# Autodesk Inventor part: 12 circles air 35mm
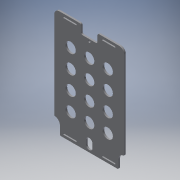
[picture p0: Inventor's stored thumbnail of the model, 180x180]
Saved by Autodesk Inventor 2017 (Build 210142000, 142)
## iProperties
Created: 2014-05
Part Number: 12 circles air 35mm
Material: Generic
Document SubType Name: Modeling
Designer: Designer
Density: 1 g/cm^3
Appearance: Default
Author: Designer
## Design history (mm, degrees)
sketch "Sketch1"
  geometry: L1 (77.642, -1.315)-(77.622, 8.185); L2 (61.622, 8.152)-(61.642, -1.348); L3 (-15.128, 22.543)-(-15.128, 233.169); L4 (49.622, 241.669)-(49.622, 227.669); L5 (53.622, 223.669)-(85.622, 223.669); L6 (89.622, 227.669)-(89.622, 241.669); L7 (-1.128, 6.669)-(-1.128, -12.331); L8 (140.372, 6.669)-(140.372, -12.331); L9 (0.872, -14.331)-(138.372, -14.331); L10 (154.372, 22.543)-(154.372, 233.169); L11 (45.622, 245.669)-(-2.628, 245.669); L12 (93.622, 245.669)-(141.872, 245.669); C1 r 3 at (69.622, 218.669); A1 r 8 centre (69.622, 8.169) between (77.622, 8.185) and (61.622, 8.152); A2 r 8 centre (69.642, -1.331) between (61.642, -1.348) and (77.642, -1.315); A3 r 4 centre (45.622, 241.669) between (49.622, 241.669) and (45.622, 245.669); A4 r 4 centre (53.622, 227.669) between (49.622, 227.669) and (53.622, 223.669); A5 r 4 centre (85.622, 227.669) between (85.622, 223.669) and (89.622, 227.669); A6 r 4 centre (93.622, 241.669) between (93.622, 245.669) and (89.622, 241.669); A7 r 14 centre (-15.128, 6.669) between (-1.128, 6.669) and (-13.378, 20.559); A8 r 2 centre (0.872, -12.331) between (-1.128, -12.331) and (0.872, -14.331); A9 r 14 centre (154.372, 6.669) between (152.622, 20.559) and (140.372, 6.669); A10 r 2 centre (138.372, -12.331) between (138.372, -14.331) and (140.372, -12.331); A11 r 2 centre (-13.128, 22.543) between (-15.128, 22.543) and (-13.378, 20.559); A12 r 2 centre (152.372, 22.543) between (152.622, 20.559) and (154.372, 22.543); A13 r 12.5 centre (-2.628, 233.169) between (-2.628, 245.669) and (-15.128, 233.169); A14 r 12.5 centre (141.872, 233.169) between (154.372, 233.169) and (141.872, 245.669); 12 further points
  constraints: 30 point on circle, 24 end point, 20 tangent, 15 centre point, 8 point on line, 4 vertical, 2 horizontal, 2 perpendicular, 2 vertical alignment, 1 midpoint, 1 parallel
  dimensions: "d111" = 5 distance from line of L5 C1.centre; "d191" = 14 distance between parallel lines of L7 L3; "d193" = 2 radius of A8 (derived); "d196" = 35 distance from line of L9 point (-15.128, 20.669); "d198" = 169.5 distance between parallel lines of L10 L3; "d199" = 260 distance between parallel lines of L9 L11; "d200" = 2 radius of A11 (derived); "d201" = 2 radius of A12 (derived); "d202" = 20 distance from line of C1.centre L4; "d203" = 12.5 radius of A13; "d244" = 4 radius of A4; "d245" = 4 radius of A5; "d246" = 4 radius of A3; "d247" = 4 radius of A6; "d248" = 215.5 distance from line of A1.centre L5; "d249" = 9.5 vertical distance of L2.start L2.end; "d250" = 9.5 vertical distance of L1.start L1.end; "d251" = 8 radius of A1; "d252" = 8 radius of A2; "d253" = 14 distance of L4.start L4.end; "d254" = 14 distance of L6.start L6.end
extrude "Extrusion1" new body sketch "Sketch1" distance "d69" = 4; taper "d70" = 0 deg
sketch "Sketch9"
  geometry: L1 (7.622, 238.169)-(37.622, 238.169); L2 (7.622, 236.669)-(37.622, 236.669); L3 (37.622, 239.669)-(7.622, 239.669); L4 (45.622, 245.669)-(-2.628, 245.669) reference; L5 (49.622, 227.669)-(49.622, 241.669) reference; L6 (101.622, 238.169)-(131.622, 238.169); L7 (101.622, 236.669)-(131.622, 236.669); L8 (131.622, 239.669)-(101.622, 239.669); L9 (89.622, 241.669)-(89.622, 227.669) reference; L10 (7.622, -8.331)-(37.622, -8.331); L11 (37.622, -5.331)-(7.622, -5.331); L12 (7.622, -6.831)-(37.622, -6.831); L13 (0.872, -14.331)-(138.372, -14.331) reference; L14 (-1.128, 6.669)-(-1.128, -12.331) reference; L15 (101.622, -8.331)-(131.622, -8.331); L16 (131.622, -5.331)-(101.622, -5.331); L17 (101.622, -6.831)-(131.622, -6.831); L18 (-15.128, 233.169)-(-15.128, 22.543) reference; L19 (85.622, 223.669)-(53.622, 223.669) reference; L20 (-15.128, 115.669)-(154.372, 115.669); L21 (154.372, 233.169)-(154.372, 22.543) reference; C1 r 12.5 at (24.622, 183.169); C2 r 3 at (69.622, 218.669) reference; C3 r 12.5 at (69.622, 183.169); C4 r 12.5 at (114.622, 183.169); C5 r 12.5 at (24.622, 138.169); C6 r 12.5 at (69.622, 138.169); C7 r 12.5 at (114.622, 138.169); C8 r 12.5 at (24.622, 93.169); C9 r 12.5 at (69.622, 93.169); C10 r 12.5 at (114.622, 93.169); C11 r 12.5 at (24.622, 48.169); C12 r 12.5 at (69.622, 48.169); C13 r 12.5 at (114.622, 48.169); A1 r 1.5 centre (7.622, 238.169) between (7.622, 239.669) and (7.622, 236.669); A2 r 1.5 centre (37.622, 238.169) between (37.622, 236.669) and (37.622, 239.669); A3 r 1.5 centre (101.622, 238.169) between (101.622, 239.669) and (101.622, 236.669); A4 r 1.5 centre (131.622, 238.169) between (131.622, 236.669) and (131.622, 239.669); A5 r 1.5 centre (37.622, -6.831) between (37.622, -8.331) and (37.622, -5.331); A6 r 1.5 centre (7.622, -6.831) between (7.622, -5.331) and (7.622, -8.331); A7 r 1.5 centre (131.622, -6.831) between (131.622, -8.331) and (131.622, -5.331); A8 r 1.5 centre (101.622, -6.831) between (101.622, -5.331) and (101.622, -8.331); 6 further points
  constraints: 34 end point, 20 centre point, 16 point on circle, 16 tangent, 12 vertical alignment, 7 horizontal alignment, 5 horizontal, 5 midpoint, 4 parallel, 2 point on line, 1 collinear
  dimensions: "d205" = 6 distance between parallel lines of L4 L3; "d206" = 12 distance from line of L5 L1.end; "d207" = 30 distance of L1.start L1.end; "d208" = 1.5 radius of A1 (derived); "d209" = 30 distance of L6.start L6.end; "d210" = 1.5 radius of A3 (derived); "d211" = 12 distance from line of L6.start L9; "d212" = 30 distance of L12.start L12.end; "d213" = 1.5 radius of A6; "d215" = 30 distance of L17.start L17.end; "d216" = 1.5 radius of A8 (derived); "d218" = 25 diameter of C1; "d220" = 25 diameter of C3; "d221" = 45 distance of C3.centre C1.centre; "d222" = 25 diameter of C4; "d223" = 45 distance of C4.centre C3.centre; "d224" = 25 diameter of C5; "d225" = 25 diameter of C6; "d226" = 45 distance of C6.centre C5.centre; "d227" = 25 diameter of C7; "d228" = 45 distance of C7.centre C6.centre; "d229" = 45 distance of C5.centre C1.centre; "d230" = 25 diameter of C8; "d231" = 25 diameter of C9; "d232" = 25 diameter of C10; "d233" = 45 distance of C9.centre C6.centre; "d234" = 25 diameter of C11; "d235" = 25 diameter of C12; "d236" = 25 diameter of C13; "d237" = 45 distance of C12.centre C9.centre; "d238" = 130 distance between parallel lines of L4 L20; "d239" = 22.5 distance from line of L20 C6.centre; "d242" = 6 distance between parallel lines of L13 L10; "d243" = 6 distance between parallel lines of L13 L15
extrude "Extrusion6" cut sketch "Sketch9" stored distance "d240" = 10; taper "d241" = 0 deg
body "Solid1"
